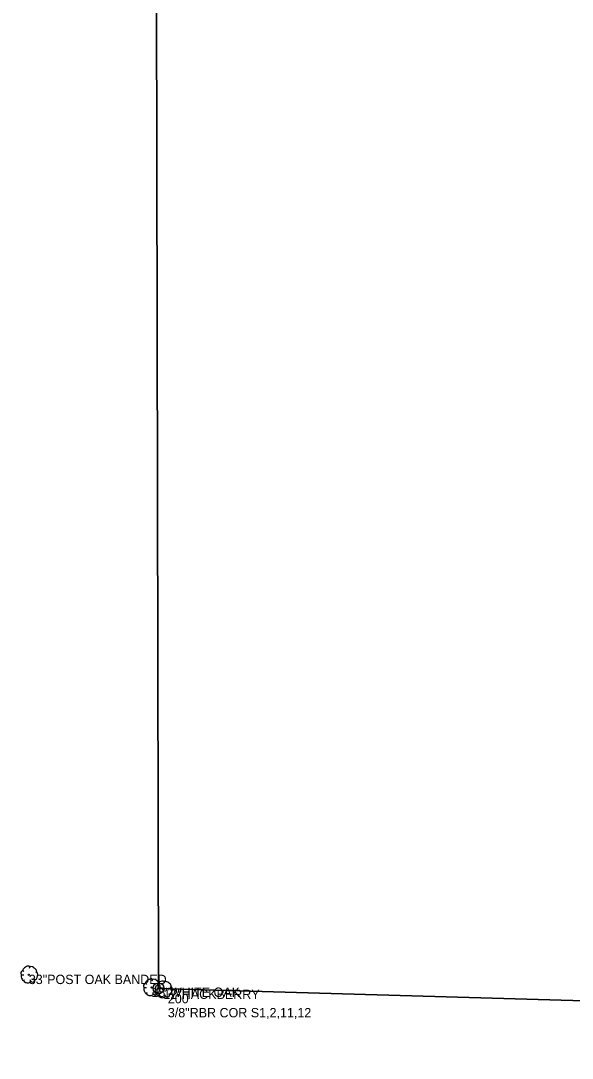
# Model space of a CAD drawing. Extents: x 1543232 to 1561726, y 1798645 to 1810340.
# Drawn here: x 1556245 to 1556835, y 1804013 to 1805123 of the extents above; entities that cross this region are included whole.
import ezdxf

# ---------------------------------------------------------------- set-up
doc = ezdxf.new("R2010")
doc.units = 0
for name, color, linetype in [('S_IRON_PIN', 7, 'Continuous'), ('S_IRON_PIN_ANNOT', 7, 'Continuous'), ('S_PROPERTY', 7, 'Continuous'), ('S_SECTION', 7, 'Continuous'), ('S_TREE', 7, 'Continuous'), ('S_TREE_ANNOT', 7, 'Continuous')]:
    doc.layers.add(name, color=color, linetype=linetype)

msp = doc.modelspace()

# ---------------------------------------------------------------- linework, layer by layer
at = {"layer": 'S_IRON_PIN'}
for radius in [5.81, 0.822, 0.523, 0.423, 0.291, 0.164, 0.116]:
    msp.add_circle((1556392.1, 1804087.9), radius, dxfattribs=at)
at = {"layer": 'S_PROPERTY'}
for p, q in [((1556392.1, 1804087.9), (1556386.4, 1806715.2)), ((1558965.2, 1804013.1), (1556392.1, 1804087.9))]:
    msp.add_line(p, q, dxfattribs=at)
at = {"layer": 'S_SECTION'}
for p, q in [((1556386.4, 1806715.2), (1556392.1, 1804087.9)), ((1556392.1, 1804087.9), (1558965.2, 1804013.1))]:
    msp.add_line(p, q, dxfattribs=at)
at = {"layer": 'S_TREE'}
for p, q in [((1556254.5, 1804111), (1556253.8, 1804109.3)), ((1556245.6, 1804102.3), (1556247.9, 1804102.3)), ((1556246.9, 1804106.9), (1556248, 1804105.8)), ((1556248, 1804095.9), (1556248.9, 1804097.3)), ((1556255.3, 1804095.4), (1556255.2, 1804096.9)), ((1556260.1, 1804097.2), (1556259.2, 1804098)), ((1556261.7, 1804105.4), (1556260.4, 1804104.8)), ((1556385.7, 1804097.3), (1556385, 1804095.6)), ((1556376.8, 1804088.7), (1556379.1, 1804088.7)), ((1556378.2, 1804093.3), (1556379.2, 1804092.1)), ((1556389.6, 1804086.4), (1556391.8, 1804086.4)), ((1556390.9, 1804091.1), (1556391.9, 1804089.9)), ((1556392.9, 1804091.8), (1556391.6, 1804091.2)), ((1556398.5, 1804095.1), (1556397.7, 1804093.4)), ((1556405.6, 1804089.5), (1556404.3, 1804089)), ((1556379.2, 1804082.3), (1556380.1, 1804083.7)), ((1556386.5, 1804081.8), (1556386.4, 1804083.3)), ((1556391.3, 1804083.5), (1556390.4, 1804084.4)), ((1556391.9, 1804080.1), (1556392.8, 1804081.5)), ((1556399.3, 1804079.5), (1556399.1, 1804081.1)), ((1556404.1, 1804081.3), (1556403.1, 1804082.2))]:
    msp.add_line(p, q, dxfattribs=at)
for centre in [(1556253.4, 1804102.5), (1556384.6, 1804088.8), (1556397.4, 1804086.6)]:
    msp.add_circle(centre, 0.681, dxfattribs=at)
for centre, major_axis, ratio, start_param, end_param in [((1556250.8, 1804108.9), (3.71, 2.17), 0.471018, 0, 3.141593), ((1556258.1, 1804108.2), (-3.63, 2.72), 0.405113, 3.141593, 6.283186), ((1556246.3, 1804104.6), (0.61, 2.05), 0.646762, 0, 3.141593), ((1556246.9, 1804099.3), (-1.22, 3.19), 0.420543, 6.283185, 9.424777), ((1556251.8, 1804095.8), (-3.66, 0.39), 0.529943, 0, 3.141593), ((1556257.7, 1804096.4), (2.18, 0.92), 0.711534, 3.141592, 6.283185), ((1556260.8, 1804101.4), (0.92, 4.08), 0.482994, 3.141593, 6.283185), ((1556382, 1804095.2), (3.71, 2.17), 0.471018, 0, 3.141593), ((1556389.3, 1804094.6), (-3.63, 2.72), 0.405113, 3.141593, 6.283186), ((1556394.7, 1804093), (3.71, 2.17), 0.471018, 0, 3.141593), ((1556377.5, 1804091), (0.61, 2.05), 0.646762, 0, 3.141593), ((1556378.1, 1804085.7), (-1.22, 3.19), 0.420543, 6.283185, 9.424777), ((1556390.2, 1804088.8), (0.61, 2.05), 0.646762, 0, 3.141593), ((1556390.8, 1804083.5), (-1.22, 3.19), 0.420543, 6.283185, 9.424777), ((1556392, 1804087.8), (0.92, 4.08), 0.482994, 3.141593, 6.283185), ((1556402, 1804092.4), (-3.63, 2.72), 0.405113, 3.141593, 6.283186), ((1556404.7, 1804085.6), (0.92, 4.08), 0.482994, 3.141593, 6.283185), ((1556383, 1804082.2), (-3.66, 0.39), 0.529943, 0, 3.141593), ((1556388.9, 1804082.7), (2.18, 0.92), 0.711534, 3.141592, 6.283185), ((1556395.8, 1804079.9), (-3.66, 0.39), 0.529943, 0, 3.141593), ((1556401.7, 1804080.5), (2.18, 0.92), 0.711534, 3.141592, 6.283185)]:
    msp.add_ellipse(centre, major_axis=major_axis, ratio=ratio, start_param=start_param, end_param=end_param, dxfattribs=at)

# ---------------------------------------------------------------- texts
at = {"layer": 'S_IRON_PIN_ANNOT'}
for s, p in [('200', (1556402.1, 1804071.9)), ('3/8"RBR COR S1,2,11,12', (1556402.1, 1804056.9))]:
    msp.add_text(s, height=10, dxfattribs=at).set_placement(p)
at = {"layer": 'S_TREE_ANNOT'}
for s, p in [('33"POST OAK BANDED', (1556253.4, 1804092.5)), ('18"WHITE OAK', (1556384.6, 1804078.8)), ('12"HACKBERRY', (1556397.4, 1804076.6))]:
    msp.add_text(s, height=10, dxfattribs=at).set_placement(p)

doc.saveas('drawing.dxf')
